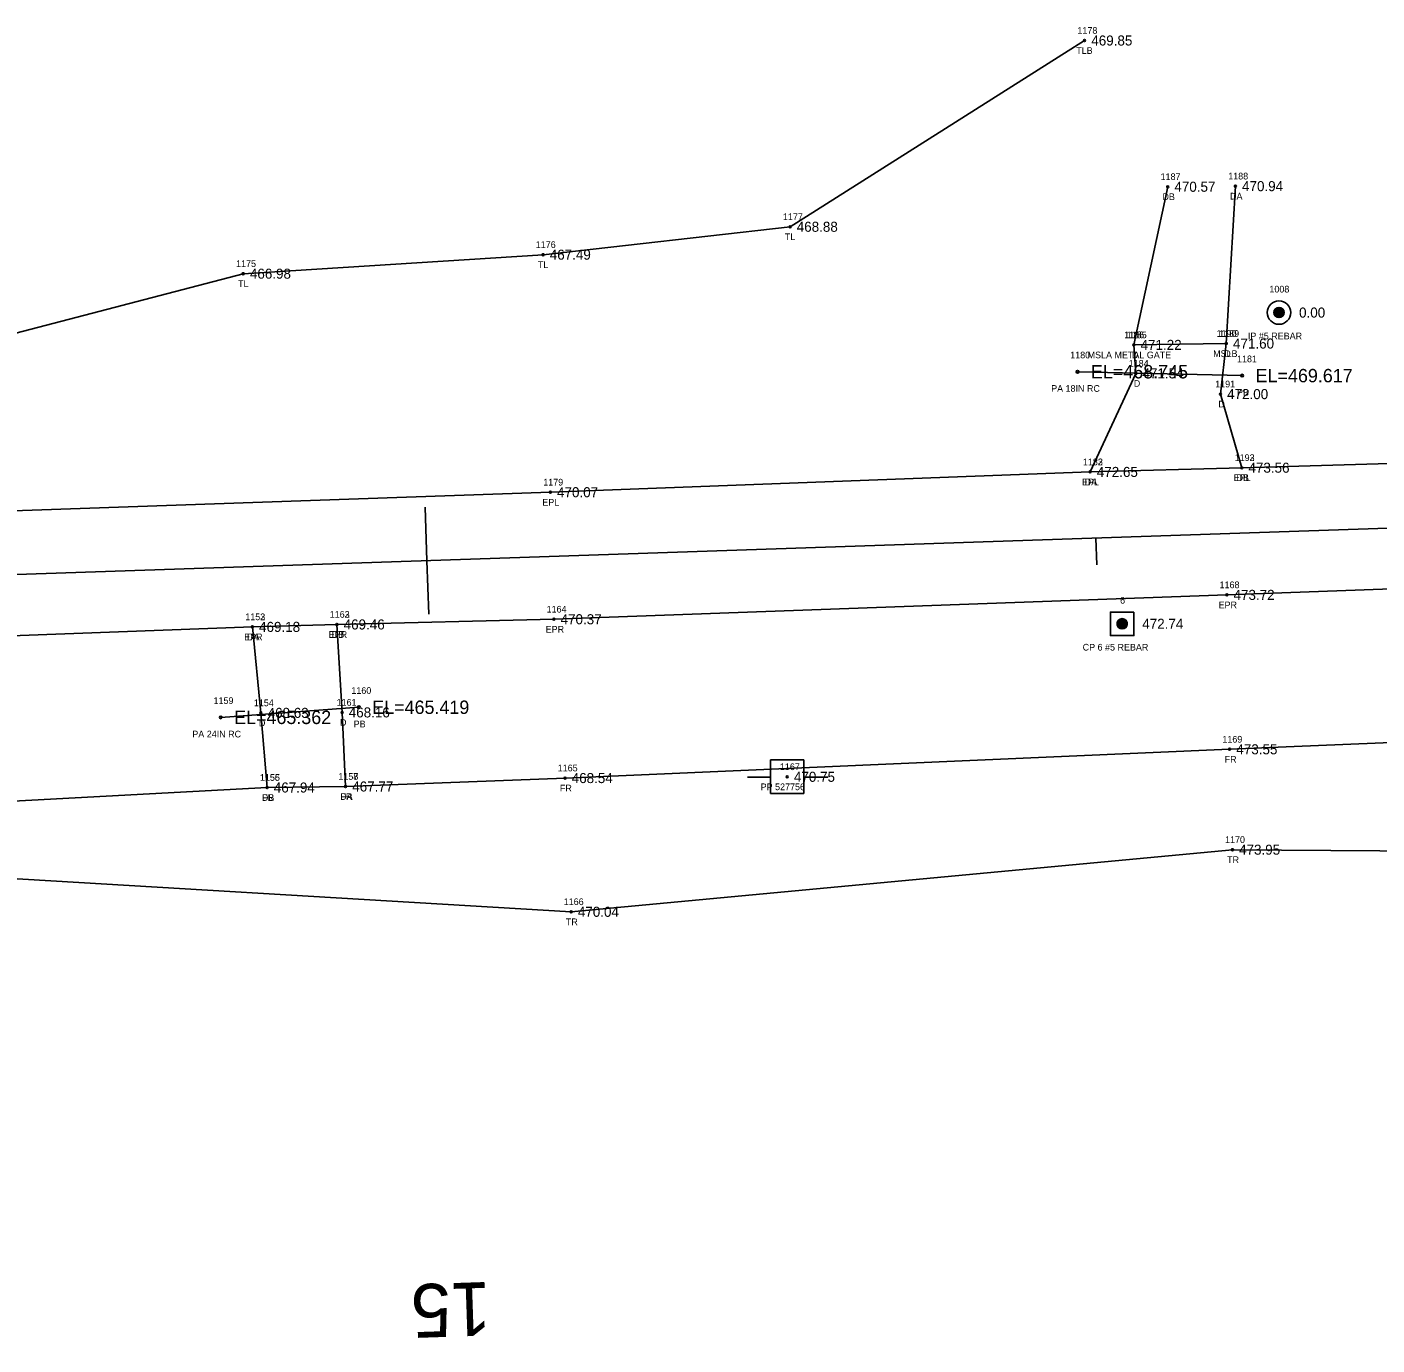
# Model space of a CAD drawing. Extents: x 1784103 to 1787401, y 770251 to 771298.
# Drawn here: x 1786199.9 to 1786401.6, y 770752.9 to 770949.8 of the extents above; entities that cross this region are included whole.
import ezdxf

# ---------------------------------------------------------------- set-up
doc = ezdxf.new("R2010")
doc.units = 0
for name, color, linetype in [('RD_EX_DR_Pipe', 7, 'Continuous'), ('RD_EX_DR_Pipe_txCode', 7, 'Continuous'), ('RD_EX_Driveway', 7, 'Continuous'), ('RD_EX_Driveway_txCode', 7, 'Continuous'), ('RD_EX_DV_Prop_txCode', 7, 'Continuous'), ('RD_EX_DV_PropPin', 7, 'Continuous'), ('RD_EX_Fence_Other', 7, 'Continuous'), ('RD_EX_Fence_Other_txCode', 7, 'Continuous'), ('RD_EX_Misc', 7, 'Continuous'), ('RD_EX_Misc_txCode', 7, 'Continuous'), ('RD_EX_Road', 7, 'Continuous'), ('RD_EX_Road_txCode', 7, 'Continuous'), ('RD_EX_TX_Driveway_ELEV', 7, 'Continuous'), ('RD_EX_TX_DV_Prop_ELEV', 7, 'Continuous'), ('RD_EX_TX_Fence_Other_ELEV', 7, 'Continuous'), ('RD_EX_TX_Misc_ELEV', 7, 'Continuous'), ('RD_EX_TX_Road_ELEV', 7, 'Continuous'), ('RD_EX_TX_VEG_ELEV', 7, 'Continuous'), ('RD_EX_UT', 7, 'Continuous'), ('RD_EX_UT_txCode', 7, 'Continuous'), ('RD_EX_VEG', 7, 'Continuous'), ('RD_EX_VEG_txCode', 7, 'Continuous'), ('RD_HC_Cl', 7, 'Continuous'), ('RD_HC_Data_Tic', 7, 'Continuous'), ('RD_HC_Survey', 7, 'Continuous'), ('RD_HC_Survey_ELEV', 7, 'Continuous'), ('RD_HC_Survey_txCode', 7, 'Continuous'), ('RD_HC_TX_Sta50', 7, 'Continuous'), ('RD_SMD_Locator', 7, 'Continuous'), ('RD_TX_Pipe_ElevEX', 7, 'Continuous')]:
    doc.layers.add(name, color=color, linetype=linetype)

msp = doc.modelspace()

# ---------------------------------------------------------------- linework, layer by layer
at = {"layer": 'RD_EX_DR_Pipe'}
for p, q in [((1786356.85, 770898.28), (1786381.45, 770897.7)), ((1786228.83, 770846.64), (1786249.47, 770848.15))]:
    msp.add_line(p, q, dxfattribs=at)
at = {"layer": 'RD_EX_Driveway'}
for points in [[(1786358.72, 770883.31), (1786365.55, 770898.03), (1786365.26, 770902.29), (1786370.31, 770925.92)], [(1786380.42, 770926.01), (1786379.07, 770902.49), (1786378.19, 770894.94), (1786381.38, 770883.94)], [(1786233.56, 770860.16), (1786234.84, 770847.31), (1786235.76, 770836.16)], [(1786247.48, 770836.31), (1786246.96, 770847.38), (1786246.2, 770860.52)]]:
    msp.add_lwpolyline(points, dxfattribs=at)
at = {"layer": 'RD_EX_DV_PropPin'}
for p, q in [((1786386.2, 770906.92), (1786386.2, 770907.32)), ((1786386.24, 770906.82), (1786386.24, 770907.42)), ((1786386.27, 770906.75), (1786386.27, 770907.49)), ((1786386.31, 770906.69), (1786386.31, 770907.55)), ((1786386.34, 770906.65), (1786386.34, 770907.59)), ((1786386.38, 770906.6), (1786386.38, 770907.63)), ((1786386.41, 770906.57), (1786386.41, 770907.67)), ((1786386.45, 770906.54), (1786386.45, 770907.7)), ((1786386.48, 770906.51), (1786386.48, 770907.73)), ((1786386.52, 770906.49), (1786386.52, 770907.75)), ((1786386.55, 770906.46), (1786386.55, 770907.78)), ((1786386.59, 770906.44), (1786386.59, 770907.8)), ((1786386.62, 770906.43), (1786386.62, 770907.81)), ((1786386.66, 770906.41), (1786386.66, 770907.83)), ((1786386.69, 770906.4), (1786386.69, 770907.84)), ((1786386.73, 770906.39), (1786386.73, 770907.85)), ((1786386.76, 770906.38), (1786386.76, 770907.86)), ((1786386.8, 770906.37), (1786386.8, 770907.87)), ((1786386.83, 770906.37), (1786386.83, 770907.87)), ((1786386.87, 770906.36), (1786386.87, 770907.88)), ((1786386.9, 770906.36), (1786386.9, 770907.88)), ((1786386.94, 770906.36), (1786386.94, 770907.88)), ((1786386.97, 770906.36), (1786386.97, 770907.88)), ((1786387.01, 770906.36), (1786387.01, 770907.88)), ((1786387.04, 770906.37), (1786387.04, 770907.87)), ((1786387.08, 770906.37), (1786387.08, 770907.87)), ((1786387.11, 770906.38), (1786387.11, 770907.86)), ((1786387.15, 770906.39), (1786387.15, 770907.85)), ((1786387.18, 770906.4), (1786387.18, 770907.84)), ((1786387.22, 770906.41), (1786387.22, 770907.83)), ((1786387.25, 770906.43), (1786387.25, 770907.81)), ((1786387.29, 770906.44), (1786387.29, 770907.8)), ((1786387.32, 770906.46), (1786387.32, 770907.78)), ((1786387.36, 770906.49), (1786387.36, 770907.75)), ((1786387.39, 770906.51), (1786387.39, 770907.73)), ((1786387.43, 770906.54), (1786387.43, 770907.7)), ((1786387.46, 770906.57), (1786387.46, 770907.67)), ((1786387.5, 770906.6), (1786387.5, 770907.63)), ((1786387.53, 770906.65), (1786387.53, 770907.59)), ((1786387.57, 770906.69), (1786387.57, 770907.55)), ((1786387.6, 770906.75), (1786387.6, 770907.49)), ((1786387.64, 770906.82), (1786387.64, 770907.42)), ((1786387.67, 770906.92), (1786387.67, 770907.32))]:
    msp.add_line(p, q, dxfattribs=at)
for radius in [1.75, 0.761]:
    msp.add_circle((1786386.94, 770907.12), radius, dxfattribs=at)
at = {"layer": 'RD_EX_Fence_Other'}
msp.add_lwpolyline([(1785232.56, 770784.32), (1785243.65, 770809.45), (1785281.87, 770810.97), (1785330.77, 770810.35), (1785381.35, 770812.32), (1785481.48, 770815.35), (1785580.21, 770817.42), (1785680.43, 770820.14), (1785794.9, 770821.68), (1785847.9, 770822.69), (1785879.84, 770822.3), (1785979.43, 770826.69), (1786080.46, 770830.52), (1786182.98, 770833.3), (1786235.76, 770836.16), (1786247.48, 770836.31), (1786280.27, 770837.57), (1786379.57, 770841.87), (1786481.1, 770846.08), (1786539.49, 770848.17), (1786546.34, 770841.89)], dxfattribs=at)
at = {"layer": 'RD_EX_Misc'}
msp.add_line((1786365.26, 770902.29), (1786379.07, 770902.49), dxfattribs=at)
at = {"layer": 'RD_EX_Road'}
for points in [[(1785824.57, 770864.86), (1785879.1, 770866.73), (1785977.08, 770869.67), (1786078.78, 770873.52), (1786179.09, 770876.83), (1786278.08, 770880.28), (1786358.72, 770883.31), (1786381.38, 770883.94), (1786478.25, 770886.75), (1786578.04, 770889.63)], [(1785825.31, 770845.6), (1785879.29, 770848.18), (1785979.17, 770851.29), (1786079.29, 770854.66), (1786178.79, 770858.1), (1786233.56, 770860.16), (1786246.2, 770860.52), (1786278.61, 770861.3), (1786379.15, 770864.94), (1786479.01, 770868.57), (1786578.78, 770871.53)]]:
    msp.add_lwpolyline(points, dxfattribs=at)
at = {"layer": 'RD_EX_UT'}
for p, q in [((1786315.96, 770840.27), (1786310.96, 770840.27)), ((1786310.96, 770840.27), (1786310.96, 770835.27)), ((1786315.96, 770835.27), (1786315.96, 770840.27)), ((1786307.53, 770837.71), (1786311, 770837.71)), ((1786315.89, 770837.71), (1786319.53, 770837.71)), ((1786310.96, 770835.27), (1786315.96, 770835.27))]:
    msp.add_line(p, q, dxfattribs=at)
at = {"layer": 'RD_EX_VEG'}
for points in [[(1785221.61, 770869.17), (1785226.44, 770862.44), (1785230.83, 770863.64), (1785281.61, 770865.88), (1785330.18, 770866.95), (1785378.64, 770865.28), (1785481.03, 770871.22), (1785579.9, 770882.43), (1785678.49, 770873.66), (1785753.25, 770880.69), (1785777.57, 770887.66), (1785796.72, 770894.6), (1785878.49, 770883.8), (1786077.63, 770894.05), (1786177.75, 770898.7), (1786232.19, 770912.93), (1786276.99, 770915.77), (1786313.89, 770919.94), (1786357.9, 770947.77)], [(1785886.65, 770752.86), (1785892.37, 770814.33), (1785979.57, 770818.93), (1786081.14, 770815.54), (1786184.19, 770823.37), (1786281.19, 770817.59), (1786379.98, 770826.87), (1786482.7, 770826.15), (1786546.34, 770841.89)]]:
    msp.add_lwpolyline(points, dxfattribs=at)
at = {"layer": 'RD_HC_Cl'}
msp.add_line((1787025.56, 770895.93), (1785279.14, 770836.9), dxfattribs=at)
at = {"layer": 'RD_HC_Data_Tic'}
for p, q in [((1786259.64, 770870.04), (1786259.37, 770878.04)), ((1786359.59, 770873.42), (1786359.72, 770869.42)), ((1786259.64, 770870.04), (1786259.91, 770862.05))]:
    msp.add_line(p, q, dxfattribs=at)
at = {"layer": 'RD_HC_Survey'}
for p, q in [((1786362.76, 770860.44), (1786362.76, 770860.8)), ((1786362.78, 770860.35), (1786362.78, 770860.88)), ((1786362.81, 770860.29), (1786362.81, 770860.94)), ((1786362.83, 770860.25), (1786362.83, 770860.99)), ((1786362.86, 770860.2), (1786362.86, 770861.03)), ((1786362.88, 770860.17), (1786362.88, 770861.07)), ((1786362.91, 770860.13), (1786362.91, 770861.1)), ((1786362.93, 770860.11), (1786362.93, 770861.13)), ((1786362.96, 770860.08), (1786362.96, 770861.15)), ((1786362.98, 770860.05), (1786362.98, 770861.18)), ((1786363.01, 770860.03), (1786363.01, 770861.2)), ((1786363.03, 770860.01), (1786363.03, 770861.22)), ((1786363.06, 770859.99), (1786363.06, 770861.24)), ((1786363.08, 770859.98), (1786363.08, 770861.26)), ((1786363.11, 770859.96), (1786363.11, 770861.27)), ((1786363.13, 770859.95), (1786363.13, 770861.29)), ((1786363.16, 770859.93), (1786363.16, 770861.3)), ((1786363.18, 770859.92), (1786363.18, 770861.31)), ((1786363.2, 770859.91), (1786363.2, 770861.32)), ((1786363.23, 770859.9), (1786363.23, 770861.33)), ((1786363.25, 770859.89), (1786363.25, 770861.34)), ((1786363.28, 770859.88), (1786363.28, 770861.35)), ((1786363.3, 770859.87), (1786363.3, 770861.36)), ((1786363.33, 770859.87), (1786363.33, 770861.36)), ((1786363.35, 770859.86), (1786363.35, 770861.37)), ((1786363.38, 770859.86), (1786363.38, 770861.37)), ((1786363.4, 770859.85), (1786363.4, 770861.38)), ((1786363.43, 770859.85), (1786363.43, 770861.38)), ((1786363.45, 770859.85), (1786363.45, 770861.38)), ((1786363.48, 770859.85), (1786363.48, 770861.39)), ((1786363.5, 770859.85), (1786363.5, 770861.39)), ((1786363.53, 770859.85), (1786363.53, 770861.39)), ((1786363.55, 770859.85), (1786363.55, 770861.38)), ((1786363.58, 770859.85), (1786363.58, 770861.38)), ((1786363.6, 770859.85), (1786363.6, 770861.38)), ((1786363.63, 770859.86), (1786363.63, 770861.38)), ((1786363.65, 770859.86), (1786363.65, 770861.37)), ((1786363.67, 770859.87), (1786363.67, 770861.37)), ((1786363.7, 770859.87), (1786363.7, 770861.36)), ((1786363.72, 770859.88), (1786363.72, 770861.35)), ((1786363.75, 770859.89), (1786363.75, 770861.35)), ((1786363.77, 770859.89), (1786363.77, 770861.34)), ((1786363.8, 770859.9), (1786363.8, 770861.33)), ((1786363.82, 770859.91), (1786363.82, 770861.32)), ((1786363.85, 770859.93), (1786363.85, 770861.31)), ((1786363.87, 770859.94), (1786363.87, 770861.29)), ((1786363.9, 770859.95), (1786363.9, 770861.28)), ((1786363.92, 770859.97), (1786363.92, 770861.26)), ((1786363.95, 770859.98), (1786363.95, 770861.25)), ((1786363.97, 770860), (1786363.97, 770861.23)), ((1786364, 770860.02), (1786364, 770861.21)), ((1786364.02, 770860.04), (1786364.02, 770861.19)), ((1786364.05, 770860.07), (1786364.05, 770861.17)), ((1786364.07, 770860.09), (1786364.07, 770861.14)), ((1786364.1, 770860.12), (1786364.1, 770861.11)), ((1786364.12, 770860.15), (1786364.12, 770861.08)), ((1786364.14, 770860.19), (1786364.14, 770861.05)), ((1786364.17, 770860.22), (1786364.17, 770861.01)), ((1786364.19, 770860.27), (1786364.19, 770860.96)), ((1786364.22, 770860.32), (1786364.22, 770860.91)), ((1786364.24, 770860.39), (1786364.24, 770860.84)), ((1786364.27, 770860.5), (1786364.27, 770860.73))]:
    msp.add_line(p, q, dxfattribs=at)
msp.add_lwpolyline([(1786365.26, 770862.37), (1786361.76, 770862.37), (1786361.76, 770858.87), (1786365.26, 770858.87)], close=True, dxfattribs=at)
msp.add_circle((1786363.51, 770860.62), 0.769, dxfattribs=at)
at = {"layer": 'RD_SMD_Locator'}
for centre, radius in [((1786357.9, 770947.77), 0.15), ((1786370.31, 770925.92), 0.15), ((1786380.42, 770926.01), 0.15), ((1786313.89, 770919.94), 0.15), ((1786276.99, 770915.77), 0.15), ((1786232.19, 770912.93), 0.15), ((1786386.94, 770907.12), 0.15), ((1786365.26, 770902.29), 0.15), ((1786365.26, 770902.29), 0.15), ((1786379.07, 770902.49), 0.15), ((1786379.07, 770902.49), 0.15), ((1786356.85, 770898.28), 0.2), ((1786365.55, 770898.03), 0.15), ((1786381.45, 770897.7), 0.2), ((1786378.19, 770894.94), 0.15), ((1786381.38, 770883.94), 0.15), ((1786381.38, 770883.94), 0.15), ((1786358.72, 770883.31), 0.15), ((1786358.72, 770883.31), 0.15), ((1786278.08, 770880.28), 0.15), ((1786379.15, 770864.94), 0.15), ((1786233.56, 770860.16), 0.15), ((1786233.56, 770860.16), 0.15), ((1786246.2, 770860.52), 0.15), ((1786246.2, 770860.52), 0.15), ((1786278.61, 770861.3), 0.15), ((1786363.51, 770860.62), 0.15), ((1786249.47, 770848.15), 0.2), ((1786228.83, 770846.64), 0.2), ((1786234.84, 770847.31), 0.15), ((1786246.96, 770847.38), 0.15), ((1786379.57, 770841.87), 0.15), ((1786280.27, 770837.57), 0.15), ((1786313.47, 770837.76), 0.15), ((1786235.76, 770836.16), 0.15), ((1786235.76, 770836.16), 0.15), ((1786247.48, 770836.31), 0.15), ((1786247.48, 770836.31), 0.15), ((1786379.98, 770826.87), 0.15), ((1786281.19, 770817.59), 0.15)]:
    msp.add_circle(centre, radius, dxfattribs=at)

# ---------------------------------------------------------------- texts
at = {"layer": 'RD_EX_DR_Pipe_txCode'}
for s, p in [('1180', (1786355.75, 770900.28)), ('1181', (1786380.67, 770899.7)), ('PA 18IN RC', (1786352.9, 770895.28)), ('PB', (1786380.67, 770894.7)), ('1160', (1786248.35, 770850.15)), ('1159', (1786227.76, 770848.64)), ('PB', (1786248.69, 770845.15)), ('PA 24IN RC', (1786224.59, 770843.64))]:
    msp.add_text(s, height=1, dxfattribs=at).set_placement(p)
at = {"layer": 'RD_EX_Driveway_txCode'}
for s, p in [('1187', (1786369.25, 770926.92)), ('1188', (1786379.36, 770927.01)), ('DB', (1786369.53, 770923.92)), ('DA', (1786379.63, 770924.01)), ('1185', (1786364.2, 770903.29)), ('1189', (1786378, 770903.49)), ('D', (1786364.96, 770900.29)), ('D', (1786378.76, 770900.49)), ('1184', (1786364.49, 770899.03)), ('D', (1786365.25, 770896.03)), ('1191', (1786377.41, 770895.94)), ('D', (1786377.89, 770892.94)), ('1183', (1786357.65, 770884.31)), ('1192', (1786380.32, 770884.94)), ('DA', (1786357.92, 770881.31)), ('DB', (1786380.6, 770881.94)), ('1153', (1786232.5, 770861.16)), ('1162', (1786245.12, 770861.52)), ('DA', (1786232.77, 770858.16)), ('DB', (1786245.42, 770858.52)), ('1154', (1786233.78, 770848.31)), ('1161', (1786246.15, 770848.38)), ('D', (1786234.54, 770845.31)), ('D', (1786246.65, 770845.38)), ('1155', (1786234.7, 770837.16)), ('1157', (1786246.41, 770837.31)), ('DB', (1786234.98, 770834.16)), ('DA', (1786246.68, 770834.31))]:
    msp.add_text(s, height=1, dxfattribs=at).set_placement(p)
at = {"layer": 'RD_EX_DV_Prop_txCode'}
for s, p in [('1008', (1786385.51, 770910.12)), ('IP #5 REBAR', (1786382.29, 770903.12))]:
    msp.add_text(s, height=1, dxfattribs=at).set_placement(p)
at = {"layer": 'RD_EX_Fence_Other_txCode'}
for s, p in [('1169', (1786378.48, 770842.87)), ('FR', (1786378.82, 770839.87)), ('1156', (1786234.68, 770837.16)), ('1158', (1786246.41, 770837.31)), ('1165', (1786279.18, 770838.57)), ('FR', (1786279.51, 770835.57)), ('FR', (1786235.01, 770834.16)), ('FR', (1786246.72, 770834.31))]:
    msp.add_text(s, height=1, dxfattribs=at).set_placement(p)
at = {"layer": 'RD_EX_Misc_txCode'}
for s, p in [('1186', (1786363.81, 770903.29)), ('1190', (1786377.62, 770903.49)), ('MSLA METAL GATE', (1786358.35, 770900.29)), ('MSLB', (1786377.1, 770900.49))]:
    msp.add_text(s, height=1, dxfattribs=at).set_placement(p)
at = {"layer": 'RD_EX_Road_txCode'}
for s, p in [('1182', (1786357.65, 770884.31)), ('1193', (1786380.32, 770884.94)), ('1179', (1786277.02, 770881.28)), ('EPL', (1786357.51, 770881.31)), ('EPL', (1786380.18, 770881.94)), ('EPL', (1786276.88, 770878.28)), ('1168', (1786378.06, 770865.94)), ('EPR', (1786377.92, 770862.94)), ('1152', (1786232.5, 770861.16)), ('1163', (1786245.12, 770861.52)), ('1164', (1786277.52, 770862.3)), ('EPR', (1786277.38, 770859.3)), ('EPR', (1786232.33, 770858.16)), ('EPR', (1786244.97, 770858.52))]:
    msp.add_text(s, height=1, dxfattribs=at).set_placement(p)
at = {"layer": 'RD_EX_TX_Driveway_ELEV'}
for s, p in [('470.57', (1786371.31, 770925.17)), ('470.94', (1786381.42, 770925.26)), ('471.22', (1786366.26, 770901.54)), ('471.60', (1786380.07, 770901.74)), ('471.54', (1786366.55, 770897.28)), ('472.00', (1786379.19, 770894.19)), ('473.56', (1786382.38, 770883.19)), ('472.65', (1786359.72, 770882.56)), ('469.18', (1786234.56, 770859.41)), ('469.46', (1786247.2, 770859.77)), ('468.63', (1786235.84, 770846.56)), ('468.16', (1786247.96, 770846.63)), ('467.94', (1786236.76, 770835.41)), ('467.77', (1786248.48, 770835.56))]:
    msp.add_text(s, height=1.5, dxfattribs=at).set_placement(p)
at = {"layer": 'RD_EX_TX_DV_Prop_ELEV'}
msp.add_text('0.00', height=1.5, dxfattribs=at).set_placement((1786389.94, 770906.37))
at = {"layer": 'RD_EX_TX_Fence_Other_ELEV'}
for s, p in [('473.55', (1786380.57, 770841.12)), ('468.54', (1786281.27, 770836.82)), ('467.94', (1786236.76, 770835.41)), ('467.77', (1786248.48, 770835.56))]:
    msp.add_text(s, height=1.5, dxfattribs=at).set_placement(p)
at = {"layer": 'RD_EX_TX_Misc_ELEV'}
for s, p in [('471.22', (1786366.26, 770901.54)), ('471.60', (1786380.07, 770901.74))]:
    msp.add_text(s, height=1.5, dxfattribs=at).set_placement(p)
at = {"layer": 'RD_EX_TX_Road_ELEV'}
for s, p in [('473.56', (1786382.38, 770883.19)), ('472.65', (1786359.72, 770882.56)), ('470.07', (1786279.08, 770879.53)), ('473.72', (1786380.15, 770864.19)), ('470.37', (1786279.61, 770860.55)), ('469.18', (1786234.56, 770859.41)), ('469.46', (1786247.2, 770859.77))]:
    msp.add_text(s, height=1.5, dxfattribs=at).set_placement(p)
at = {"layer": 'RD_EX_TX_VEG_ELEV'}
for s, p in [('469.85', (1786358.9, 770947.02)), ('468.88', (1786314.89, 770919.19)), ('467.49', (1786277.99, 770915.02)), ('466.98', (1786233.19, 770912.18)), ('473.95', (1786380.98, 770826.12)), ('470.04', (1786282.19, 770816.84))]:
    msp.add_text(s, height=1.5, dxfattribs=at).set_placement(p)
at = {"layer": 'RD_EX_UT_txCode'}
for s, p in [('1167', (1786312.38, 770838.76)), ('PP 527756', (1786309.5, 770835.76))]:
    msp.add_text(s, height=1, dxfattribs=at).set_placement(p)
at = {"layer": 'RD_EX_VEG_txCode'}
for s, p in [('1178', (1786356.83, 770948.77)), ('TLB', (1786356.65, 770945.77)), ('1177', (1786312.83, 770920.94)), ('TL', (1786313.12, 770917.94)), ('1176', (1786275.9, 770916.77)), ('1175', (1786231.13, 770913.93)), ('TL', (1786276.22, 770913.77)), ('TL', (1786231.42, 770910.93)), ('1170', (1786378.88, 770827.87)), ('TR', (1786379.19, 770824.87)), ('1166', (1786280.08, 770818.59)), ('TR', (1786280.4, 770815.59))]:
    msp.add_text(s, height=1, dxfattribs=at).set_placement(p)
at = {"layer": 'RD_HC_Survey_ELEV'}
for s, p in [('472.74', (1786366.51, 770859.87)), ('470.75', (1786314.47, 770837.01))]:
    msp.add_text(s, height=1.5, dxfattribs=at).set_placement(p)
at = {"layer": 'RD_HC_Survey_txCode'}
for s, p in [('6', (1786363.2, 770863.62)), ('CP 6 #5 REBAR', (1786357.61, 770856.62))]:
    msp.add_text(s, height=1, dxfattribs=at).set_placement(p)
at = {"layer": 'RD_HC_TX_Sta50'}
msp.add_text('15', height=8, rotation=181.9359, dxfattribs=at).set_placement((1786269.05, 770762.3))
at = {"layer": 'RD_TX_Pipe_ElevEX'}
for s, p in [('EL=468.745', (1786358.85, 770897.28)), ('EL=469.617', (1786383.45, 770896.7)), ('EL=465.419', (1786251.47, 770847.15)), ('EL=465.362', (1786230.83, 770845.64))]:
    msp.add_text(s, height=2, dxfattribs=at).set_placement(p)

doc.saveas('drawing.dxf')
